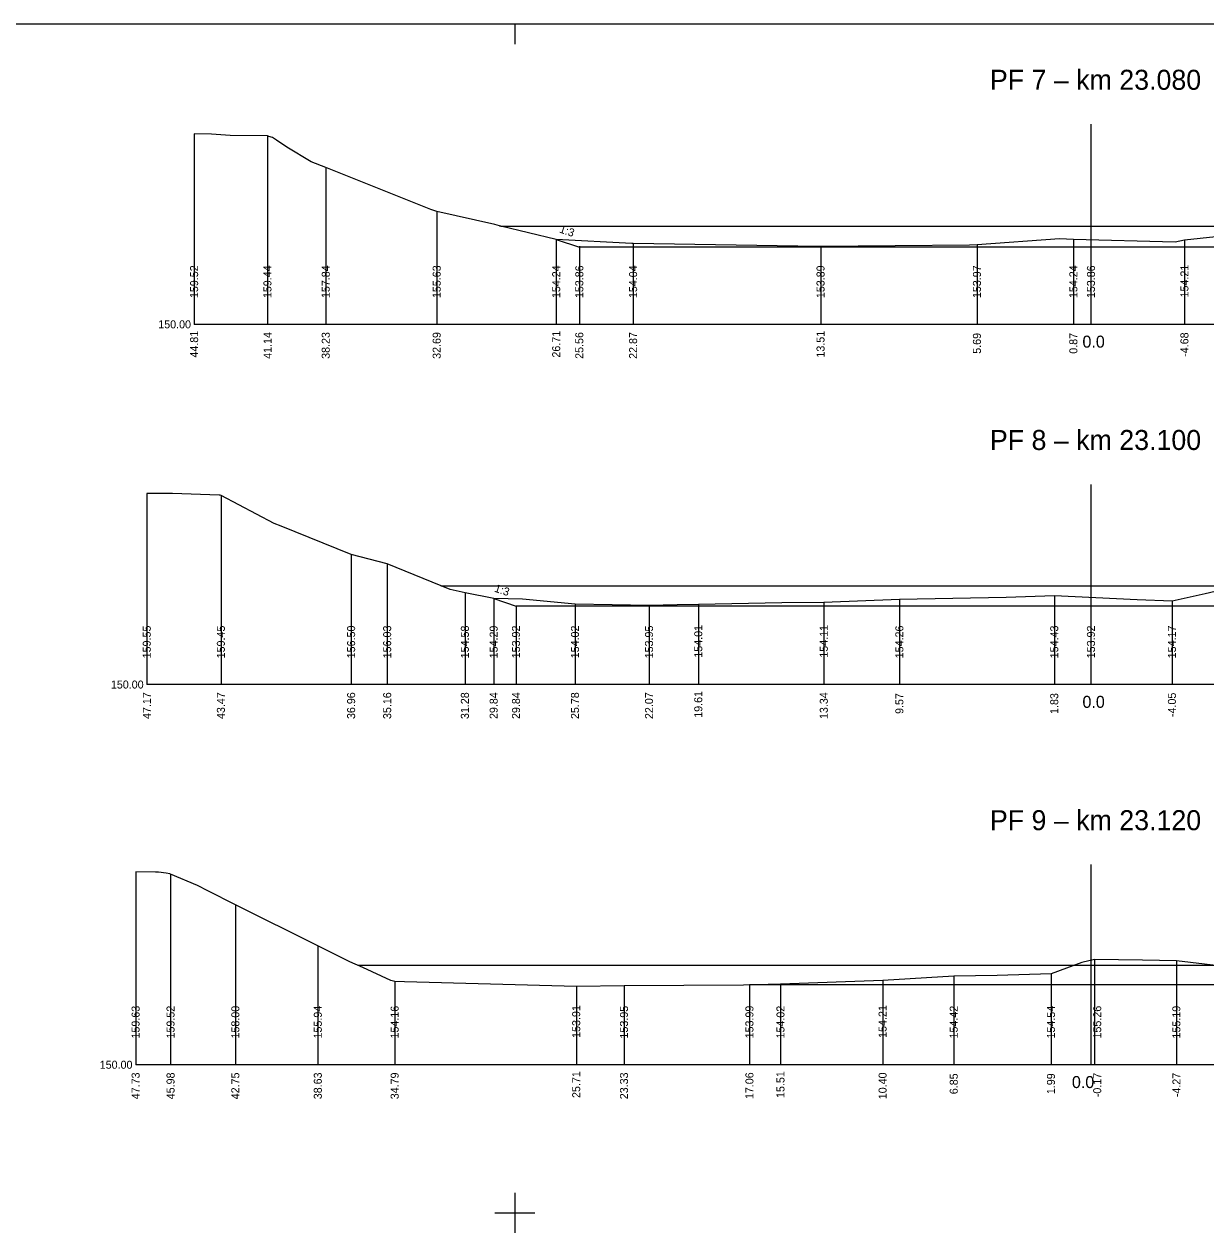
# Model space of a CAD drawing. Extents: x -582678 to -581845, y -1210354 to -1210235.
# Drawn here: x -582576 to -582517, y -1210295.7 to -1210235.3 of the extents above; entities that cross this region are included whole.
import ezdxf

# ---------------------------------------------------------------- set-up
doc = ezdxf.new("R2010")
doc.units = 0
for name, color, linetype in [('_N_osa', 7, 'Continuous'), ('_N_popis', 7, 'Continuous'), ('_N_tučná', 7, 'Continuous'), ('_rámeček', 7, 'Continuous'), ('_S_hladina', 7, 'Continuous'), ('_S_popis', 7, 'Continuous'), ('_S_popis_oprav!', 7, 'Continuous'), ('_S_tenká', 7, 'Continuous'), ('_S_velmi_tenká', 7, 'Continuous')]:
    doc.layers.add(name, color=color, linetype=linetype)

msp = doc.modelspace()

# ---------------------------------------------------------------- linework, layer by layer
at = {"layer": '_N_osa'}
for p, q in [((-582522.722, -1210240.291), (-582522.722, -1210250.291)), ((-582522.722, -1210258.291), (-582522.722, -1210268.291)), ((-582522.722, -1210277.291), (-582522.722, -1210287.291))]:
    msp.add_line(p, q, dxfattribs=at)
at = {"layer": '_N_popis'}
for points in [[(-582549.436, -1210246.046), (-582549.436, -1210250.291), (-582549.436, -1210250.291), (-582549.436, -1210250.291)], [(-582548.281, -1210246.385), (-582548.281, -1210250.291), (-582548.281, -1210250.291), (-582548.281, -1210250.291)], [(-582552.561, -1210263.999), (-582552.561, -1210268.291), (-582552.561, -1210268.291), (-582552.561, -1210268.291)], [(-582551.445, -1210264.371), (-582551.445, -1210268.291), (-582551.445, -1210268.291), (-582551.445, -1210268.291)], [(-582539.78, -1210283.301), (-582539.78, -1210287.284), (-582539.78, -1210287.284), (-582539.78, -1210287.284)]]:
    msp.add_lwpolyline(points, dxfattribs=at)
at = {"layer": '_N_tučná'}
for p, q in [((-582549.436, -1210246.046), (-582548.281, -1210246.431)), ((-582552.561, -1210263.999), (-582551.445, -1210264.371))]:
    msp.add_line(p, q, dxfattribs=at)
for points in [[(-582489.976, -1210246.431), (-582548.281, -1210246.431)], [(-582486.869, -1210264.371), (-582551.445, -1210264.371)], [(-582484.328, -1210283.301), (-582539.78, -1210283.301)]]:
    msp.add_lwpolyline(points, dxfattribs=at)
at = {"layer": '_rámeček'}
for p, q in [((-582467.502, -1210235.291), (-582677.502, -1210235.291)), ((-582551.502, -1210235.291), (-582551.502, -1210236.291)), ((-582551.502, -1210293.691), (-582551.502, -1210295.691)), ((-582552.502, -1210294.691), (-582550.502, -1210294.691))]:
    msp.add_line(p, q, dxfattribs=at)
at = {"layer": '_S_hladina'}
msp.add_line((-582523.567, -1210282.321), (-582516.554, -1210282.321), dxfattribs=at)
for points in [[(-582552.213, -1210245.381), (-582487.268, -1210245.381)], [(-582555.2, -1210263.351), (-582484.431, -1210263.351)], [(-582559.354, -1210282.321), (-582523.567, -1210282.321)]]:
    msp.add_lwpolyline(points, dxfattribs=at)
at = {"layer": '_S_tenká'}
for p, q in [((-582472.722, -1210250.291), (-582567.528, -1210250.291)), ((-582472.722, -1210268.291), (-582569.895, -1210268.291)), ((-582472.722, -1210287.291), (-582570.452, -1210287.291))]:
    msp.add_line(p, q, dxfattribs=at)
for points in [[(-582516.482, -1210245.92), (-582518.043, -1210246.078), (-582518.521, -1210246.179), (-582523.593, -1210246.051), (-582524.289, -1210246.018), (-582528.413, -1210246.319), (-582528.795, -1210246.327), (-582536.227, -1210246.403), (-582536.335, -1210246.408), (-582545.593, -1210246.251), (-582545.629, -1210246.252), (-582545.66, -1210246.251), (-582549.436, -1210246.046), (-582552.213, -1210245.381), (-582552.251, -1210245.377), (-582552.272, -1210245.373), (-582552.507, -1210245.295), (-582555.407, -1210244.66), (-582555.705, -1210244.545), (-582560.952, -1210242.45), (-582561.689, -1210242.176), (-582562.904, -1210241.433), (-582563.418, -1210241.089), (-582563.614, -1210240.953), (-582563.798, -1210240.9), (-582563.864, -1210240.876), (-582565.727, -1210240.85), (-582566.67, -1210240.79), (-582567.528, -1210240.775)], [(-582516.021, -1210263.52), (-582517.019, -1210263.764), (-582518.668, -1210264.123), (-582520.418, -1210264.055), (-582524.55, -1210263.865), (-582526.958, -1210263.942), (-582532.288, -1210264.035), (-582536.064, -1210264.184), (-582538.171, -1210264.213), (-582542.337, -1210264.284), (-582543.399, -1210264.312), (-582544.796, -1210264.337), (-582548.497, -1210264.267), (-582551.133, -1210264.024), (-582552.561, -1210263.999), (-582553.999, -1210263.716), (-582554.747, -1210263.536), (-582557.882, -1210262.257), (-582559.683, -1210261.796), (-582563.187, -1210260.372), (-582563.539, -1210260.24), (-582566.191, -1210258.843), (-582566.232, -1210258.821), (-582566.234, -1210258.821), (-582566.239, -1210258.821), (-582566.288, -1210258.82), (-582568.612, -1210258.746), (-582569.895, -1210258.744)], [(-582515.644, -1210282.426), (-582518.448, -1210282.103), (-582520.141, -1210282.066), (-582522.549, -1210282.03), (-582523.172, -1210282.174), (-582524.713, -1210282.748), (-582527.4, -1210282.839), (-582529.572, -1210282.872), (-582533.126, -1210283.077), (-582538.229, -1210283.267), (-582540.086, -1210283.308), (-582546.049, -1210283.341), (-582548.436, -1210283.383), (-582557.019, -1210283.145), (-582557.508, -1210283.135), (-582557.708, -1210283.088), (-582559.104, -1210282.433), (-582559.754, -1210282.141), (-582561.349, -1210281.353), (-582565.47, -1210279.296), (-582566.842, -1210278.605), (-582567.37, -1210278.34), (-582568.707, -1210277.775), (-582568.753, -1210277.752), (-582568.925, -1210277.712), (-582569.307, -1210277.666), (-582569.472, -1210277.661), (-582570.452, -1210277.656)]]:
    msp.add_lwpolyline(points, dxfattribs=at)
at = {"layer": '_S_velmi_tenká'}
for points in [[(-582567.528, -1210240.775), (-582567.528, -1210250.291), (-582567.528, -1210250.291), (-582567.528, -1210250.291)], [(-582563.864, -1210240.876), (-582563.864, -1210250.291), (-582563.864, -1210250.291), (-582563.864, -1210250.291)], [(-582560.952, -1210242.45), (-582560.952, -1210250.291), (-582560.952, -1210250.291), (-582560.952, -1210250.291)], [(-582555.407, -1210244.66), (-582555.407, -1210250.291), (-582555.407, -1210250.291), (-582555.407, -1210250.291)], [(-582545.593, -1210246.251), (-582545.593, -1210250.291), (-582545.593, -1210250.291), (-582545.593, -1210250.291)], [(-582523.593, -1210246.051), (-582523.593, -1210250.291), (-582523.593, -1210250.291), (-582523.593, -1210250.291)], [(-582518.043, -1210246.078), (-582518.043, -1210250.291), (-582518.043, -1210250.291), (-582518.043, -1210250.291)], [(-582536.227, -1210246.403), (-582536.227, -1210250.291), (-582536.227, -1210250.291), (-582536.227, -1210250.291)], [(-582528.413, -1210246.319), (-582528.413, -1210250.291), (-582528.413, -1210250.291), (-582528.413, -1210250.291)], [(-582569.895, -1210258.744), (-582569.895, -1210268.291), (-582569.895, -1210268.291), (-582569.895, -1210268.291)], [(-582566.191, -1210258.843), (-582566.191, -1210268.291), (-582566.191, -1210268.291), (-582566.191, -1210268.291)], [(-582559.683, -1210261.796), (-582559.683, -1210268.291), (-582559.683, -1210268.291), (-582559.683, -1210268.291)], [(-582557.882, -1210262.257), (-582557.882, -1210268.291), (-582557.882, -1210268.291), (-582557.882, -1210268.291)], [(-582553.999, -1210263.716), (-582553.999, -1210268.291), (-582553.999, -1210268.291), (-582553.999, -1210268.291)], [(-582548.497, -1210264.267), (-582548.497, -1210268.291), (-582548.497, -1210268.291), (-582548.497, -1210268.291)], [(-582544.796, -1210264.337), (-582544.796, -1210268.291), (-582544.796, -1210268.291), (-582544.796, -1210268.291)], [(-582542.337, -1210264.284), (-582542.337, -1210268.291), (-582542.337, -1210268.291), (-582542.337, -1210268.291)], [(-582536.064, -1210264.184), (-582536.064, -1210268.291), (-582536.064, -1210268.291), (-582536.064, -1210268.291)], [(-582532.288, -1210264.035), (-582532.288, -1210268.291), (-582532.288, -1210268.291), (-582532.288, -1210268.291)], [(-582524.55, -1210263.865), (-582524.55, -1210268.291), (-582524.55, -1210268.291), (-582524.55, -1210268.291)], [(-582518.668, -1210264.123), (-582518.668, -1210268.291), (-582518.668, -1210268.291), (-582518.668, -1210268.291)], [(-582570.452, -1210277.656), (-582570.452, -1210287.291), (-582570.452, -1210287.291), (-582570.452, -1210287.291)], [(-582568.707, -1210277.775), (-582568.707, -1210287.291), (-582568.707, -1210287.291), (-582568.707, -1210287.291)], [(-582565.47, -1210279.296), (-582565.47, -1210287.291), (-582565.47, -1210287.291), (-582565.47, -1210287.291)], [(-582561.349, -1210281.353), (-582561.349, -1210287.291), (-582561.349, -1210287.291), (-582561.349, -1210287.291)], [(-582522.549, -1210282.03), (-582522.549, -1210287.291), (-582522.549, -1210287.291), (-582522.549, -1210287.291)], [(-582518.448, -1210282.103), (-582518.448, -1210287.291), (-582518.448, -1210287.291), (-582518.448, -1210287.291)], [(-582533.126, -1210283.077), (-582533.126, -1210287.291), (-582533.126, -1210287.291), (-582533.126, -1210287.291)], [(-582529.572, -1210282.872), (-582529.572, -1210287.291), (-582529.572, -1210287.291), (-582529.572, -1210287.291)], [(-582524.713, -1210282.748), (-582524.713, -1210287.291), (-582524.713, -1210287.291), (-582524.713, -1210287.291)], [(-582557.508, -1210283.145), (-582557.508, -1210287.291), (-582557.508, -1210287.291), (-582557.508, -1210287.291)], [(-582548.436, -1210283.383), (-582548.436, -1210287.291), (-582548.436, -1210287.291), (-582548.436, -1210287.291)], [(-582546.049, -1210283.341), (-582546.049, -1210287.291), (-582546.049, -1210287.291), (-582546.049, -1210287.291)], [(-582538.229, -1210283.267), (-582538.229, -1210287.291), (-582538.229, -1210287.291), (-582538.229, -1210287.291)]]:
    msp.add_lwpolyline(points, dxfattribs=at)

# ---------------------------------------------------------------- texts
at = {"layer": '_N_popis'}
for s, height, rotation, p in [('1:3', 0.4, 341.56505, (-582549.316, -1210245.694)), ('154.24', 0.4, 90, (-582549.242, -1210248.981)), ('153.86', 0.4, 90, (-582548.088, -1210248.981)), ('153.86', 0.4, 90, (-582522.522, -1210248.981)), ('26.71', 0.4, 90, (-582549.242, -1210251.953)), ('25.56', 0.4, 90, (-582548.088, -1210252.016)), ('0.0', 0.6, 360, (-582523.146, -1210251.456)), ('1:3', 0.4, 341.56505, (-582552.562, -1210263.642)), ('154.29', 0.4, 90, (-582552.368, -1210266.982)), ('153.92', 0.4, 90, (-582551.251, -1210266.98)), ('153.92', 0.4, 90, (-582522.522, -1210266.98)), ('29.84', 0.4, 90, (-582552.368, -1210270.015)), ('29.84', 0.4, 90, (-582551.251, -1210270.015)), ('0.0', 0.6, 360, (-582523.146, -1210269.456)), ('153.99', 0.4, 90, (-582539.587, -1210285.975)), ('17.06', 0.4, 90, (-582539.587, -1210289.009)), ('0.0', 0.6, 360, (-582523.672, -1210288.456))]:
    msp.add_text(s, height=height, rotation=rotation, dxfattribs=at).set_placement(p)
at = {"layer": '_S_popis'}
for s, p in [('159.52', (-582567.335, -1210248.98)), ('159.44', (-582563.671, -1210248.981)), ('157.84', (-582560.759, -1210248.981)), ('155.63', (-582555.214, -1210248.981)), ('154.04', (-582545.4, -1210248.981)), ('153.89', (-582536.034, -1210248.982)), ('153.97', (-582528.219, -1210248.981)), ('154.24', (-582523.4, -1210248.981)), ('154.21', (-582517.85, -1210248.949)), ('44.81', (-582567.335, -1210251.953)), ('41.14', (-582563.664, -1210252.015)), ('38.23', (-582560.759, -1210252.016)), ('32.69', (-582555.214, -1210252.017)), ('22.87', (-582545.4, -1210252.016)), ('13.51', (-582536.034, -1210251.953)), ('5.69', (-582528.219, -1210251.762)), ('0.87', (-582523.4, -1210251.761)), ('-4.68', (-582517.85, -1210251.915)), ('159.55', (-582569.702, -1210266.982)), ('159.45', (-582565.998, -1210266.982)), ('156.50', (-582559.49, -1210266.981)), ('156.03', (-582557.688, -1210266.981)), ('154.58', (-582553.806, -1210266.982)), ('154.02', (-582548.304, -1210266.98)), ('153.95', (-582544.603, -1210266.982)), ('154.01', (-582542.143, -1210266.949)), ('154.11', (-582535.871, -1210266.949)), ('154.26', (-582532.095, -1210266.981)), ('154.43', (-582524.356, -1210266.981)), ('154.17', (-582518.475, -1210266.981)), ('47.17', (-582569.695, -1210270.016)), ('43.47', (-582565.998, -1210270.016)), ('36.96', (-582559.49, -1210270.016)), ('35.16', (-582557.688, -1210270.016)), ('31.28', (-582553.806, -1210270.017)), ('25.78', (-582548.304, -1210270.017)), ('22.07', (-582544.603, -1210270.016)), ('19.61', (-582542.143, -1210269.953)), ('13.34', (-582535.871, -1210270.015)), ('9.57', (-582532.095, -1210269.761)), ('1.83', (-582524.356, -1210269.761)), ('-4.05', (-582518.475, -1210269.916)), ('159.63', (-582570.259, -1210285.981)), ('159.52', (-582568.513, -1210285.98)), ('158.00', (-582565.276, -1210285.981)), ('155.94', (-582561.155, -1210285.981)), ('154.16', (-582557.315, -1210285.981)), ('153.91', (-582548.243, -1210285.949)), ('153.95', (-582545.856, -1210285.982)), ('154.02', (-582538.036, -1210285.98)), ('154.21', (-582532.933, -1210285.949)), ('154.42', (-582529.379, -1210285.98)), ('154.54', (-582524.52, -1210285.981)), ('155.26', (-582522.207, -1210285.981)), ('155.19', (-582518.255, -1210285.982)), ('47.73', (-582570.259, -1210289.016)), ('45.98', (-582568.513, -1210289.017)), ('42.75', (-582565.276, -1210289.019)), ('38.63', (-582561.155, -1210289.016)), ('34.79', (-582557.315, -1210289.017)), ('25.71', (-582548.243, -1210288.953)), ('23.33', (-582545.856, -1210289.016)), ('15.51', (-582538.036, -1210288.953)), ('10.40', (-582532.933, -1210289.015)), ('6.85', (-582529.379, -1210288.764)), ('1.99', (-582524.52, -1210288.762)), ('-0.17', (-582522.207, -1210288.914)), ('-4.27', (-582518.248, -1210288.914))]:
    msp.add_text(s, height=0.4, rotation=90, dxfattribs=at).set_placement(p)
for p in [(-582569.327, -1210250.491), (-582571.694, -1210268.491), (-582572.251, -1210287.491)]:
    msp.add_text('150.00', height=0.4, dxfattribs=at).set_placement(p)
at = {"layer": '_S_popis_oprav!'}
for s, p in [('PF 7 – km 23.080', (-582527.77, -1210238.57)), ('PF 8 – km 23.100', (-582527.77, -1210256.57)), ('PF 9 – km 23.120', (-582527.77, -1210275.57))]:
    msp.add_text(s, height=1, dxfattribs=at).set_placement(p)

doc.saveas('drawing.dxf')
